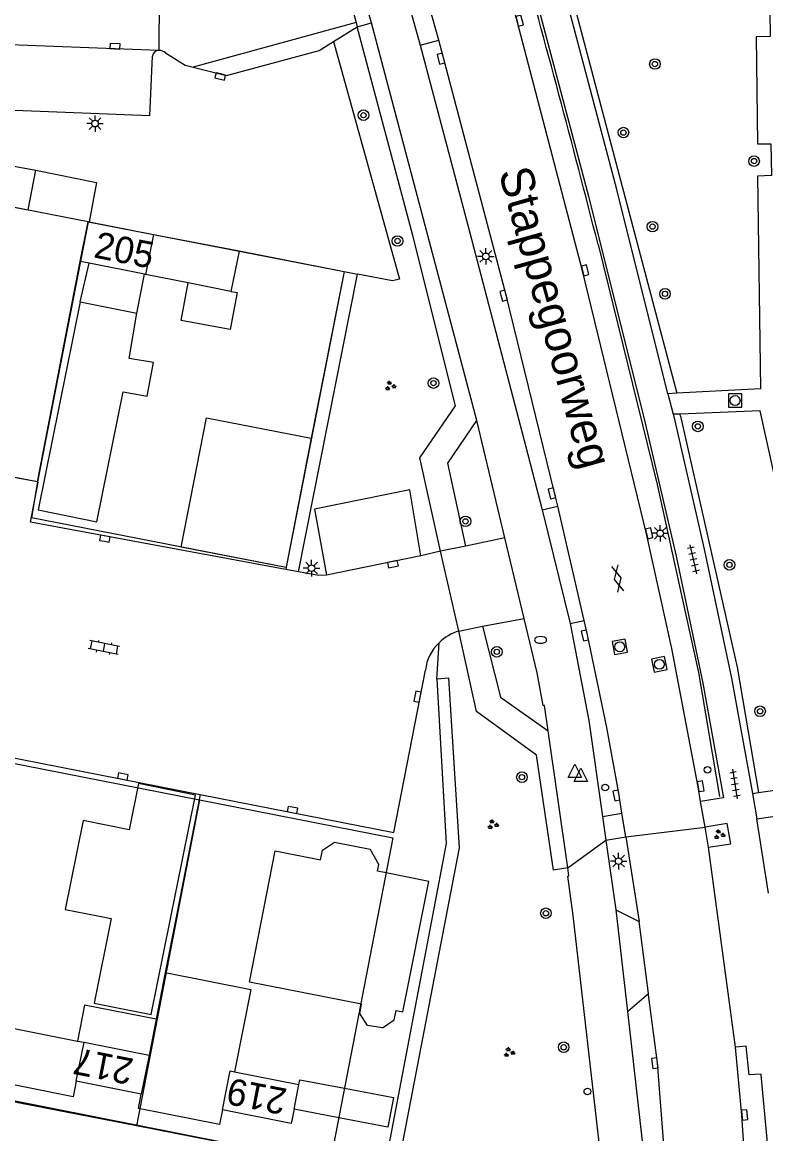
# Model space of a CAD drawing. Extents: x 132994 to 136000, y 393499 to 395512.
# Drawn here: x 133826.5 to 133882.7, y 394483.5 to 394567.4 of the extents above; entities that cross this region are included whole.
import ezdxf

# ---------------------------------------------------------------- set-up
doc = ezdxf.new("R2010")
doc.units = 0
for name, color, linetype in [('gg-afsc-erfafscheiding', 7, 'Continuous'), ('gg-afsc-hekwerk', 7, 'Continuous'), ('gg-afsc-muur', 7, 'Continuous'), ('gg-anno-openbare ruimte label', 7, 'Continuous'), ('gg-bbg-bijgebouw', 7, 'Continuous'), ('gg-bbg-gedigitaliseerde bijgebouw', 7, 'Continuous'), ('gg-bbg-hoofdgebouw', 7, 'Continuous'), ('gg-bbg-luifel en loopbrug', 7, 'Continuous'), ('gg-bbg-overig bouwwerk', 7, 'Continuous'), ('gg-bbg-tussenscheiding', 7, 'Continuous'), ('gg-knt-verharding', 7, 'Continuous'), ('gg-knt-verharding nz', 7, 'Continuous'), ('gt-afsc-standplaatsafbakening', 7, 'Continuous'), ('gt-anno-standplaatsnummer', 7, 'Continuous'), ('gt-grn-groengrens', 7, 'Continuous'), ('gt-grn-vlakafsluiter', 7, 'Continuous'), ('gt-grn-weggrens', 7, 'Continuous'), ('gt-symb-boom', 7, 'Continuous'), ('gt-symb-brandkraan', 7, 'Continuous'), ('gt-symb-gesloten verharding', 7, 'Continuous'), ('gt-symb-groenvak', 7, 'Continuous'), ('gt-symb-klinker verharding', 7, 'Continuous'), ('gt-symb-kolk', 7, 'Continuous'), ('gt-symb-lichtmast', 7, 'Continuous'), ('gt-symb-rioolschacht', 7, 'Continuous'), ('gt-symb-tegel verharding', 7, 'Continuous'), ('gt-symb-verkeersbordpaal', 7, 'Continuous'), ('gt-symb-waterafsluiter', 7, 'Continuous')]:
    doc.layers.add(name, color=color, linetype=linetype)

# ---------------------------------------------------------------- blocks, each defined once
blk = doc.blocks.new('gt0-BOOM')
at = {"layer": 'gt-symb-boom'}
for radius in [0.4, 0.2]:
    blk.add_circle((0, 0), radius, dxfattribs=at)
blk = doc.blocks.new('gt0-RS')
at = {"layer": 'gt-symb-rioolschacht'}
blk.add_lwpolyline([(-0.5, -0.5), (0.5, -0.5), (0.5, 0.5), (-0.5, 0.5)], close=True, dxfattribs=at)
blk.add_circle((0, 0), 0.375, dxfattribs=at)
blk = doc.blocks.new('gt0-KOLK')
at = {"layer": 'gt-symb-kolk'}
blk.add_lwpolyline([(0, 0), (0.375, 0), (0.375, 0.4), (-0.375, 0.4), (-0.375, 0), (0, 0)], dxfattribs=at)
blk = doc.blocks.new('gt0-LMAST')
at = {"layer": 'gt-symb-lichtmast'}
for p, q in [((-0.182, 0.173), (-0.447, 0.438)), ((-0.005, 0.246), (-0.005, 0.621)), ((0.172, 0.173), (0.437, 0.438)), ((-0.255, -0.004), (-0.63, -0.004)), ((-0.182, -0.181), (-0.447, -0.446)), ((-0.005, -0.254), (-0.005, -0.629)), ((0.437, -0.446), (0.172, -0.181)), ((0.245, -0.004), (0.62, -0.004))]:
    blk.add_line(p, q, dxfattribs=at)
blk.add_circle((-0.005, -0.004), 0.25, dxfattribs=at)
blk = doc.blocks.new('gt0-TEG1')
at = {"layer": 'gt-symb-tegel verharding'}
for p, q in [((-1.125, 0), (1.125, 0)), ((-0.9, -0.25), (-0.9, 0.25)), ((-0.45, -0.25), (-0.45, 0.25)), ((0, -0.25), (0, 0.25)), ((0.45, -0.25), (0.45, 0.25)), ((0.9, -0.25), (0.9, 0.25))]:
    blk.add_line(p, q, dxfattribs=at)
blk = doc.blocks.new('gt0-VPAAL')
at = {"layer": 'gt-symb-verkeersbordpaal'}
blk.add_circle((0, 0), 0.25, dxfattribs=at)
blk = doc.blocks.new('gt0-KL1')
at = {"layer": 'gt-symb-klinker verharding'}
for p, q in [((-1.15, 0.3), (1.15, 0.3)), ((-1, -0.3), (-1, 0.3)), ((-0.5, 0.3), (-0.5, 0.45)), ((0, -0.3), (0, 0.3)), ((0.5, 0.3), (0.5, 0.45)), ((1, -0.3), (1, 0.3)), ((-1.15, -0.3), (1.15, -0.3)), ((-0.5, -0.45), (-0.5, -0.3)), ((0.5, -0.45), (0.5, -0.3))]:
    blk.add_line(p, q, dxfattribs=at)
blk = doc.blocks.new('gt0-GRVAK')
at = {"layer": 'gt-symb-groenvak'}
for p, q in [((-0.11, 0.189), (-0.228, 0.24)), ((-0.182, 0.153), (0.088, 0.153)), ((-0.091, 0.211), (-0.156, 0.322)), ((-0.047, 0.214), (-0.047, 0.393)), ((-0.004, 0.211), (0.061, 0.322)), ((0.015, 0.189), (0.133, 0.24)), ((0.262, -0.052), (0.197, 0.059)), ((0.305, -0.049), (0.305, 0.13)), ((0.349, -0.052), (0.414, 0.059)), ((-0.245, -0.228), (-0.363, -0.177)), ((-0.318, -0.264), (-0.047, -0.264)), ((-0.226, -0.206), (-0.291, -0.095)), ((-0.183, -0.203), (-0.183, -0.024)), ((-0.139, -0.206), (-0.074, -0.095)), ((-0.12, -0.228), (-0.002, -0.177)), ((0.243, -0.074), (0.125, -0.023)), ((0.17, -0.11), (0.441, -0.11)), ((0.368, -0.074), (0.486, -0.023))]:
    blk.add_line(p, q, dxfattribs=at)
blk = doc.blocks.new('gt0-GESVH1')
at = {"layer": 'gt-symb-gesloten verharding'}
for p, q in [((-0.992, -0.261), (0.008, 0.239)), ((0.008, -0.261), (-0.992, 0.239)), ((0.008, 0.239), (1.008, -0.261)), ((1.008, 0.239), (0.008, -0.261))]:
    blk.add_line(p, q, dxfattribs=at)
blk = doc.blocks.new('gt0-BR')
at = {"layer": 'gt-symb-brandkraan'}
for centre, radius, start, end in [((-0.244, 0), 0.206, 107.56694, 252.43307), ((0.599, -2.664), 3, 106.89205, 107.56694), ((0, -0.691), 0.938, 73.10799, 106.89205), ((-0.599, -2.664), 3, 72.43309, 73.10799), ((0.244, 0), 0.206, 287.56695, 72.43309), ((0.599, 2.664), 3, 252.43307, 253.10797), ((0, 0.691), 0.938, 253.10797, 286.89206), ((-0.599, 2.664), 3, 286.89206, 287.56695)]:
    blk.add_arc(centre, radius, start, end, dxfattribs=at)
blk = doc.blocks.new('gt0-WAFSL')
at = {"layer": 'gt-symb-waterafsluiter'}
for p, q in [((-0.5, -0.333), (0, 0.667)), ((0, 0.667), (0.5, -0.333)), ((0.5, -0.333), (-0.5, -0.333))]:
    blk.add_line(p, q, dxfattribs=at)

msp = doc.modelspace()

# ---------------------------------------------------------------- linework, layer by layer
at = {"layer": 'gg-afsc-erfafscheiding'}
for p, q in [((133827.573, 394556.257), (133832.152, 394555.315)), ((133827.682, 394532.726), (133830.903, 394549.366)), ((133839.977, 394509.139), (133838.179, 394500)), ((133838.179, 394500), (133837.334, 394495.705))]:
    msp.add_line(p, q, dxfattribs=at)
at = {"layer": 'gg-afsc-hekwerk'}
for p, q in [((133850.836, 394548.607), (133851.84, 394548.411)), ((133857.506, 394500), (133853.862, 394480.877))]:
    msp.add_line(p, q, dxfattribs=at)
for points in [[(133850.016, 394565.948), (133855.003, 394548.03), (133854.47, 394547.896), (133851.84, 394548.411)], [(133869.999, 394550.631), (133874.445, 394532.538), (133876.044, 394525.319), (133877.562, 394518.351), (133879.169, 394508.991)], [(133857.83, 394517.841), (133858.541, 394505.433), (133857.506, 394500)], [(133851.487, 394480.936), (133812.538, 394488.672), (133766.776, 394497.285)]]:
    msp.add_lwpolyline(points, dxfattribs=at)
msp.add_arc((132808.383, 394279.749), 1095.63, 14.314151, 15.540182, dxfattribs=at)
at = {"layer": 'gg-afsc-muur'}
for p, q in [((133832.152, 394555.315), (133831.587, 394552.341)), ((133842.903, 394550.158), (133850.836, 394548.607)), ((133850.836, 394548.607), (133848.355, 394536.032))]:
    msp.add_line(p, q, dxfattribs=at)
at = {"layer": 'gg-bbg-bijgebouw'}
for p, q in [((133848.355, 394536.032), (133846.458, 394526.296)), ((133846.458, 394526.296), (133846.452, 394526.267)), ((133850.425, 394484.741), (133847.052, 394485.388))]:
    msp.add_line(p, q, dxfattribs=at)
for points in [[(133846.452, 394526.267), (133838.539, 394527.811), (133840.445, 394537.573), (133848.355, 394536.032)], [(133830.616, 394487.512), (133830.378, 394486.326), (133820.368, 394488.335), (133820.606, 394489.521)], [(133847.424, 394487.255), (133847.494, 394487.621), (133850.858, 394486.976)], [(133850.858, 394486.976), (133854.549, 394486.269), (133854.121, 394484.033), (133850.425, 394484.741)], [(133841.651, 394485.349), (133841.433, 394484.239), (133835.305, 394485.444), (133835.518, 394486.528)]]:
    msp.add_lwpolyline(points, dxfattribs=at)
at = {"layer": 'gg-bbg-gedigitaliseerde bijgebouw'}
for p, q in [((133837.334, 394495.705), (133836.642, 394492.185)), ((133821.174, 394492.414), (133830.717, 394490.538))]:
    msp.add_line(p, q, dxfattribs=at)
for points in [[(133837.334, 394495.705), (133843.782, 394494.437), (133842.561, 394488.223)], [(133836.642, 394492.185), (133831.249, 394493.245), (133830.717, 394490.538)]]:
    msp.add_lwpolyline(points, dxfattribs=at)
at = {"layer": 'gg-bbg-hoofdgebouw'}
for p, q in [((133831.587, 394552.341), (133836.434, 394551.406)), ((133836.434, 394551.406), (133842.903, 394550.158)), ((133842.901, 394550.147), (133842.288, 394547.106)), ((133842.903, 394550.158), (133842.901, 394550.147)), ((133831.58, 394549.232), (133830.903, 394549.366)), ((133835.772, 394548.399), (133831.58, 394549.232)), ((133835.834, 394548.387), (133835.772, 394548.399)), ((133839.056, 394547.747), (133835.834, 394548.387)), ((133842.288, 394547.106), (133839.056, 394547.747)), ((133842.561, 394488.223), (133847.424, 394487.255)), ((133835.518, 394486.528), (133830.616, 394487.512))]:
    msp.add_line(p, q, dxfattribs=at)
for points in [[(133830.903, 394549.366), (133831.524, 394552.353), (133831.587, 394552.341)], [(133847.052, 394485.388), (133846.839, 394484.316), (133841.651, 394485.349)]]:
    msp.add_lwpolyline(points, dxfattribs=at)
at = {"layer": 'gg-bbg-luifel en loopbrug'}
for p, q in [((133822.501, 394557.148), (133827.573, 394556.257)), ((133830.918, 394546.328), (133831.58, 394549.232)), ((133835.179, 394545.467), (133835.772, 394548.399)), ((133830.918, 394546.328), (133835.179, 394545.467))]:
    msp.add_line(p, q, dxfattribs=at)
for points in [[(133821.931, 394554.21), (133826.992, 394553.257), (133827.573, 394556.257)], [(133842.288, 394547.106), (133842.746, 394547.022), (133842.232, 394544.223), (133838.534, 394544.902), (133839.056, 394547.747)]]:
    msp.add_lwpolyline(points, dxfattribs=at)
at = {"layer": 'gg-bbg-overig bouwwerk'}
for points in [[(133830.918, 394546.328), (133827.744, 394530.621), (133832.175, 394529.707), (133834.152, 394539.528), (133835.963, 394539.189), (133836.441, 394541.745), (133834.616, 394542.046), (133835.179, 394545.467)], [(133832.12, 394500), (133833.248, 394499.772), (133831.961, 394493.402), (133836.262, 394492.533), (133839.607, 394509.089), (133835.305, 394509.958), (133834.601, 394506.469), (133831.124, 394507.171), (133829.771, 394500.475), (133832.12, 394500)], [(133853.729, 394491.521), (133852.589, 394491.703), (133852.005, 394492.606), (133852.145, 394493.318), (133843.682, 394494.981), (133845.629, 394504.889), (133849.054, 394504.216), (133849.196, 394504.938), (133850.092, 394505.541), (133852.783, 394505.012)], [(133854.002, 394503.221), (133853.349, 394503.353), (133853.442, 394503.867), (133852.783, 394505.012)], [(133853.729, 394491.521), (133854.61, 394492.138), (133854.748, 394492.85), (133855.256, 394492.752), (133857.234, 394502.57), (133854.002, 394503.221)]]:
    msp.add_lwpolyline(points, dxfattribs=at)
at = {"layer": 'gg-bbg-tussenscheiding'}
for p, q in [((133836.434, 394551.406), (133835.834, 394548.387)), ((133836.642, 394492.185), (133836.11, 394489.478)), ((133830.616, 394487.512), (133831.204, 394490.442)), ((133830.717, 394490.538), (133831.204, 394490.442)), ((133831.204, 394490.442), (133836.11, 394489.478)), ((133836.11, 394489.478), (133835.518, 394486.528)), ((133847.052, 394485.388), (133847.424, 394487.255))]:
    msp.add_line(p, q, dxfattribs=at)
msp.add_lwpolyline([(133841.651, 394485.349), (133842.236, 394488.288), (133842.561, 394488.223)], dxfattribs=at)
at = {"layer": 'gg-knt-verharding'}
for p, q in [((133853.094, 394578.346), (133856.563, 394565.688)), ((133857.971, 394566.061), (133854.439, 394578.722)), ((133852.884, 394567.361), (133850.739, 394575.18)), ((133849.744, 394574.622), (133851.731, 394567.391)), ((133851.731, 394567.391), (133851.817, 394567.077)), ((133850.016, 394565.948), (133851.817, 394567.077)), ((133856.563, 394565.688), (133857.971, 394566.061)), ((133858.326, 394564.72), (133857.971, 394566.061)), ((133836.171, 394560.353), (133836.376, 394564.858)), ((133836.841, 394565.286), (133836.856, 394565.285)), ((133836.171, 394560.353), (133795.485, 394561.908)), ((133875.938, 394539.422), (133875.253, 394539.386)), ((133827.682, 394532.726), (133803.75, 394537.359)), ((133862.971, 394528.51), (133860.848, 394537.355)), ((133876.191, 394537.851), (133875.66, 394537.831)), ((133875.66, 394537.831), (133875.701, 394537.673)), ((133865.787, 394530.63), (133866.949, 394530.901)), ((133865.787, 394530.63), (133867.888, 394522.034)), ((133868.956, 394522.273), (133866.949, 394530.901)), ((133860.008, 394527.882), (133858.098, 394527.492)), ((133862.971, 394528.51), (133860.008, 394527.882)), ((133864.43, 394522.42), (133862.971, 394528.51)), ((133858.098, 394527.492), (133856.615, 394527.159)), ((133859.483, 394521.469), (133858.098, 394527.492)), ((133847.394, 394525.934), (133846.424, 394526.114)), ((133861.263, 394521.845), (133864.43, 394522.42)), ((133867.888, 394522.034), (133868.956, 394522.273)), ((133859.483, 394521.469), (133861.263, 394521.845)), ((133867.703, 394503.595), (133866.225, 394513.938)), ((133824.868, 394512.111), (133839.977, 394509.139)), ((133882.096, 394509.289), (133888.388, 394510.226)), ((133878.076, 394506.672), (133877.737, 394508.615)), ((133881.65, 394509.223), (133882.096, 394509.289)), ((133870.325, 394507.49), (133871.797, 394507.724)), ((133870.325, 394507.49), (133870.572, 394505.702)), ((133872.08, 394505.941), (133871.797, 394507.724)), ((133881.982, 394507.295), (133883.195, 394507.471)), ((133882.847, 394501.692), (133881.982, 394507.295)), ((133878.339, 394505.163), (133878.076, 394506.672)), ((133870.572, 394505.702), (133872.08, 394505.941)), ((133870.572, 394505.702), (133871.333, 394500.446)), ((133872.08, 394505.941), (133873.085, 394499.567)), ((133878.339, 394505.163), (133880.007, 394505.407)), ((133880.365, 394490.065), (133878.339, 394505.163)), ((133871.333, 394500.446), (133872.216, 394492.761)), ((133871.333, 394500.446), (133873.085, 394499.567)), ((133873.799, 394494.112), (133873.085, 394499.567)), ((133872.216, 394492.761), (133873.799, 394494.112)), ((133873.812, 394494.013), (133873.799, 394494.112)), ((133872.216, 394492.761), (133873.53, 394481.271))]:
    msp.add_line(p, q, dxfattribs=at)
for points in [[(133877.737, 394508.615), (133877.544, 394509.725), (133875.554, 394520.151), (133873.658, 394528.802), (133868.832, 394548.651), (133863.881, 394567.488), (133858.37, 394587.197), (133852.336, 394606.728), (133849.435, 394615.44)], [(133851.279, 394615.928), (133855.833, 394601.963), (133860.503, 394586.249), (133865.14, 394569.833), (133869.277, 394554.279), (133873.551, 394537.169), (133875.879, 394527.123), (133877.905, 394517.53), (133879.45, 394508.878), (133877.737, 394508.615)], [(133875.253, 394539.386), (133871.412, 394554.798), (133867.291, 394570.392), (133862.612, 394586.817), (133857.902, 394602.588), (133857.252, 394604.589)], [(133881.039, 394578.969), (133881.159, 394570.157), (133882.945, 394570.187), (133882.994, 394566.329), (133881.922, 394566.301), (133882.039, 394558.231), (133883.039, 394558.234), (133883.072, 394555.854), (133882.037, 394555.8), (133882.245, 394539.749), (133875.938, 394539.422)], [(133860.848, 394537.355), (133857.054, 394551.694), (133852.884, 394567.361)], [(133858.098, 394527.492), (133856.549, 394534.533), (133859.235, 394538.478), (133856.005, 394551.323), (133851.817, 394567.077)], [(133839.44, 394564.022), (133841.955, 394563.404), (133848.957, 394565.285), (133850.016, 394565.948)], [(133856.563, 394565.688), (133860.167, 394552.089), (133864.706, 394534.799), (133865.787, 394530.63)], [(133837.358, 394565.104), (133838.824, 394564.173), (133839.44, 394564.022)], [(133866.949, 394530.901), (133866.714, 394531.907), (133863.061, 394546.825), (133858.326, 394564.72)], [(133888.388, 394510.226), (133882.239, 394538.08), (133876.191, 394537.851)], [(133860.008, 394527.882), (133858.649, 394534.137), (133860.848, 394537.355)], [(133875.701, 394537.673), (133878.001, 394527.66), (133880.077, 394517.924), (133881.65, 394509.223)], [(133846.424, 394526.114), (133827.161, 394529.693), (133827.743, 394532.714), (133827.682, 394532.726)], [(133856.615, 394527.159), (133855.799, 394532.125), (133848.582, 394530.659), (133849.488, 394525.699)], [(133849.488, 394525.699), (133848.899, 394525.654), (133847.394, 394525.934)], [(133866.225, 394513.938), (133865.94, 394515.846), (133865.851, 394515.848), (133865.393, 394518.316), (133864.43, 394522.42)], [(133867.888, 394522.034), (133869.3, 394514.718), (133870.325, 394507.49)], [(133871.797, 394507.724), (133871.58, 394509.096), (133870.646, 394514.206), (133869.201, 394521.176), (133868.956, 394522.273)], [(133867.703, 394503.595), (133866.634, 394503.422), (133865.345, 394512.115), (133860.821, 394515.413), (133859.483, 394521.469)], [(133861.263, 394521.845), (133862.639, 394516.497), (133866.225, 394513.938)], [(133839.977, 394509.139), (133854.591, 394506.264), (133856.966, 394518.534)], [(133880.007, 394505.407), (133879.749, 394506.942), (133878.076, 394506.672)], [(133870.259, 394481.348), (133868.119, 394500.007), (133867.704, 394502.989), (133867.79, 394502.994), (133867.703, 394503.595)], [(133875.058, 394481.389), (133874.477, 394488.888), (133873.812, 394494.013)], [(133882.305, 394487.991), (133882.302, 394488.032), (133881.393, 394487.975), (133881.179, 394490.145), (133880.365, 394490.065)], [(133885.833, 394415.226), (133884.952, 394423.7), (133883.355, 394444.153), (133882.193, 394464.546), (133880.853, 394484.941), (133880.365, 394490.065)], [(133885.833, 394415.226), (133886.965, 394415.281), (133887.29, 394415.466), (133887.51, 394415.769), (133887.564, 394416.416), (133886.513, 394427.358), (133885.229, 394444.207), (133884.958, 394449.146), (133884.612, 394453.936), (133883.88, 394465.991), (133883.588, 394472.266), (133883.074, 394479.619), (133882.305, 394487.991)]]:
    msp.add_lwpolyline(points, dxfattribs=at)
for centre, radius, start, end in [((133836.83, 394564.832), 0.455, 88.58569, 176.66911), ((133836.865, 394564.523), 0.762, 49.68055, 90.66512), ((133860.37, 394518.313), 3.278, 105.70288, 136.15615), ((133860.251, 394518.156), 3.307, 132.76188, 173.43921)]:
    msp.add_arc(centre, radius, start, end, dxfattribs=at)
at = {"layer": 'gg-knt-verharding nz'}
for p, q in [((133836.895, 394571.29), (133836.856, 394565.285)), ((133851.731, 394567.391), (133839.44, 394564.022)), ((133851.817, 394567.077), (133852.884, 394567.361)), ((133856.615, 394527.159), (133849.488, 394525.699))]:
    msp.add_line(p, q, dxfattribs=at)
msp.add_lwpolyline([(133836.841, 394565.286), (133823.617, 394565.776), (133811.811, 394566.256), (133795.668, 394566.851), (133795.485, 394561.908)], dxfattribs=at)
at = {"layer": 'gt-afsc-standplaatsafbakening'}
for p, q in [((133831.524, 394552.355), (133821.931, 394554.21)), ((133831.524, 394552.355), (133827.682, 394532.726)), ((133831.524, 394552.355), (133850.836, 394548.607)), ((133850.836, 394548.607), (133846.457, 394526.296)), ((133827.682, 394532.726), (133812.931, 394535.451)), ((133827.682, 394532.726), (133827.229, 394530.046)), ((133827.229, 394530.046), (133846.457, 394526.296)), ((133825.206, 394511.636), (133839.924, 394508.741)), ((133839.924, 394508.741), (133835.172, 394484.131)), ((133835.172, 394484.131), (133820.451, 394487.008))]:
    msp.add_line(p, q, dxfattribs=at)
msp.add_lwpolyline([(133839.924, 394508.741), (133854.515, 394505.871), (133849.755, 394481.28), (133835.172, 394484.131)], dxfattribs=at)
at = {"layer": 'gt-grn-groengrens'}
for p, q in [((133847.394, 394525.934), (133851.84, 394548.411)), ((133876.222, 394537.7), (133876.191, 394537.851))]:
    msp.add_line(p, q, dxfattribs=at)
for points in [[(133857.564, 394604.762), (133865.959, 394577.2), (133875.938, 394539.422)], [(133876.222, 394537.7), (133880.499, 394518.737), (133882.096, 394509.289)], [(133870.259, 394481.348), (133855.108, 394482.104), (133859.533, 394505.108), (133858.74, 394517.915), (133857.83, 394517.841)]]:
    msp.add_lwpolyline(points, dxfattribs=at)
at = {"layer": 'gt-grn-vlakafsluiter'}
for p, q in [((133846.452, 394526.267), (133846.424, 394526.114)), ((133857.83, 394517.841), (133858.006, 394520.584))]:
    msp.add_line(p, q, dxfattribs=at)
at = {"layer": 'gt-grn-weggrens'}
for p, q in [((133875.253, 394539.386), (133875.66, 394537.831)), ((133881.65, 394509.223), (133881.982, 394507.295)), ((133872.08, 394505.941), (133878.076, 394506.672)), ((133867.703, 394503.595), (133870.572, 394505.702))]:
    msp.add_line(p, q, dxfattribs=at)

# ---------------------------------------------------------------- block references
at = {"layer": 'gt-symb-boom'}
for p in [(133874.287, 394564.261), (133852.296, 394560.398), (133871.908, 394559.088), (133881.766, 394556.936), (133874.106, 394551.99), (133854.857, 394550.908), (133875.047, 394546.922), (133857.574, 394540.183), (133877.525, 394536.917), (133859.993, 394529.751), (133879.915, 394526.47), (133862.353, 394519.907), (133882.22, 394515.421), (133864.25, 394510.45), (133866.059, 394500.181), (133867.401, 394490.068)]:
    msp.add_blockref('gt0-BOOM', p, dxfattribs=at)
at = {"layer": 'gt-symb-brandkraan'}
msp.add_blockref('gt0-BR', (133865.658, 394520.806), dxfattribs=at)
at = {"layer": 'gt-symb-gesloten verharding', "rotation": 102.93881062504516}
msp.add_blockref('gt0-GESVH1', (133871.473, 394525.422), dxfattribs=at)
at = {"layer": 'gt-symb-groenvak'}
for p in [(133854.304, 394539.973), (133862.043, 394506.87), (133879.135, 394506.115), (133863.274, 394489.676)]:
    msp.add_blockref('gt0-GRVAK', p, dxfattribs=at)
at = {"layer": 'gt-symb-klinker verharding', "rotation": 168.57767893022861}
msp.add_blockref('gt0-KL1', (133832.699, 394520.233), dxfattribs=at)
at = {"layer": 'gt-symb-kolk'}
for p, rotation in [((133863.881, 394567.488), -75.28268885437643), ((133833.532, 394565.406), -2.11482401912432), ((133858.326, 394564.72), 104.81913788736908), ((133841.526, 394563.51), 166.20450190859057), ((133868.832, 394548.651), -76.35276166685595), ((133863.061, 394546.825), 104.82810852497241), ((133866.714, 394531.907), 103.77214543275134), ((133873.658, 394528.802), -77.64517308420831), ((133832.74, 394528.247), -10.489389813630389), ((133854.555, 394526.33), 11.422321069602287), ((133869.201, 394521.176), 102.53502335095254), ((133856.568, 394516.483), 78.92612884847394), ((133834.093, 394510.299), -11.186329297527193), ((133871.58, 394509.096), 100.36632260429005), ((133877.544, 394509.725), -80.15137761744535), ((133846.887, 394507.78), -11.242525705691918), ((133874.477, 394488.888), 97.4091840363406), ((133880.853, 394484.941), -84.54608111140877)]:
    msp.add_blockref('gt0-KOLK', p, dxfattribs=dict(at, rotation=rotation))
at = {"layer": 'gt-symb-lichtmast'}
for p in [(133832.035, 394559.768), (133861.53, 394549.75), (133874.69, 394528.853), (133848.38, 394526.23), (133871.553, 394504.119)]:
    msp.add_blockref('gt0-LMAST', p, dxfattribs=at)
at = {"layer": 'gt-symb-rioolschacht'}
msp.add_blockref('gt0-RS', (133880.335, 394538.865), dxfattribs=at)
for p, rotation in [((133871.631, 394520.287), 100.25359802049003), ((133874.625, 394518.962), -168.17329607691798)]:
    msp.add_blockref('gt0-RS', p, dxfattribs=dict(at, rotation=rotation))
at = {"layer": 'gt-symb-tegel verharding'}
for p, rotation in [((133877.2, 394526.877), 102.93881062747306), ((133880.323, 394509.936), -80.8486039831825)]:
    msp.add_blockref('gt0-TEG1', p, dxfattribs=dict(at, rotation=rotation))
at = {"layer": 'gt-symb-verkeersbordpaal'}
for p in [(133878.252, 394511.007), (133870.541, 394509.662), (133869.188, 394486.734)]:
    msp.add_blockref('gt0-VPAAL', p, dxfattribs=at)
at = {"layer": 'gt-symb-waterafsluiter'}
for p in [(133868.247, 394510.766), (133868.685, 394510.462)]:
    msp.add_blockref('gt0-WAFSL', p, dxfattribs=at)

# ---------------------------------------------------------------- texts
at = {"layer": 'gg-anno-openbare ruimte label'}
msp.add_text('Stappegoorweg', height=2.5, rotation=285.5, dxfattribs=at).set_placement((133862.472, 394556.107))
at = {"layer": 'gt-anno-standplaatsnummer'}
for s, rotation, p in [('205', 348.88094, (133831.862, 394549.678)), ('217', 168.92613, (133835.033, 394489.181)), ('219', 168.92613, (133846.612, 394486.912))]:
    msp.add_text(s, height=2, rotation=rotation, dxfattribs=at).set_placement(p)

doc.saveas('drawing.dxf')
